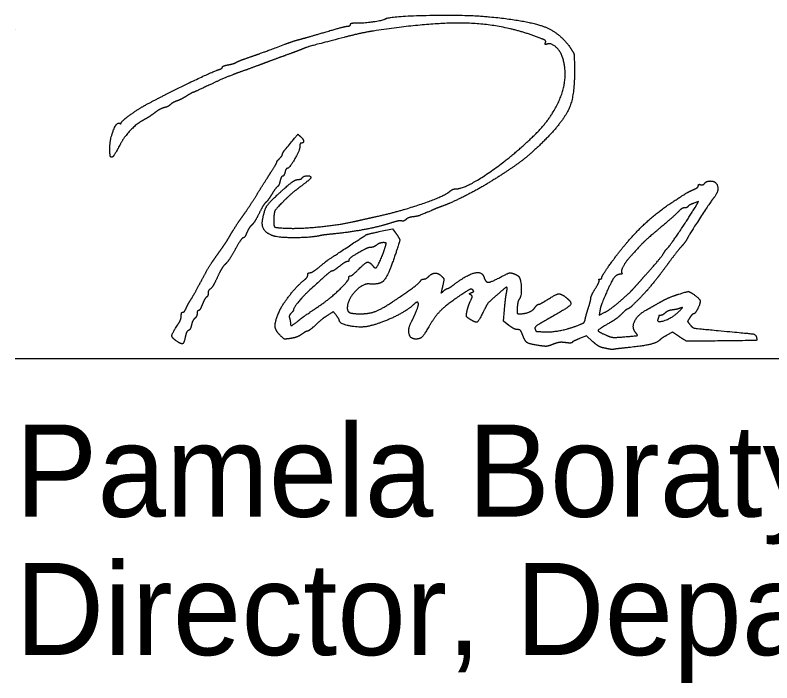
# Model space of a CAD drawing. Extents: x -11.1 to 43.5, y 0 to 22.
# Drawn here: x 24.5 to 25.648, y 7.199 to 8.213 of the extents above; entities that cross this region are included whole.
import ezdxf

# ---------------------------------------------------------------- set-up
doc = ezdxf.new("R2010")
doc.units = 0
doc.layers.add('SH_Data', color=7, linetype='Continuous')
doc.layers.add('SH_Text', color=7, linetype='Continuous')

msp = doc.modelspace()

# ---------------------------------------------------------------- linework, layer by layer
at = {"layer": 'SH_Data'}
for p, q in [((24.5, 8.191), (24.5, 8.191)), ((24.5, 7.691), (28, 7.691))]:
    msp.add_line(p, q, dxfattribs=at)
at = {"layer": 'SH_Text'}
for points in [[(25.5318, 7.9205), (25.5372, 7.9294), (25.5298, 7.9268)], [(25.0545, 7.8843), (25.0725, 7.8883), (25.0772, 7.8822)], [(25.2494, 7.7415), (25.2411, 7.7478), (25.2426, 7.7649)], [(25.3874, 7.7635), (25.3864, 7.757), (25.3951, 7.7614)], [(25.5083, 7.7242), (25.4976, 7.731), (25.4892, 7.7264)], [(25.3764, 7.7172), (25.3672, 7.7254), (25.3567, 7.7214)]]:
    msp.add_lwpolyline(points, dxfattribs=at)
for points in [[(25.0619, 8.2069), (25.0687, 8.2111), (25.1857, 8.2134), (25.2201, 8.21)], [(25.0089, 8.1984), (25.0089, 8.1998), (25.0129, 8.2008), (25.0179, 8.2007)], [(25.0179, 8.2007), (25.0275, 8.2004), (25.0585, 8.2047), (25.0619, 8.2069)], [(25.2926, 8.1792), (25.242, 8.1982), (25.1341, 8.2022), (25.0437, 8.1884)], [(25.2201, 8.21), (25.2794, 8.2041), (25.3269, 8.1858), (25.3427, 8.1628)], [(24.9721, 8.1873), (24.9882, 8.192), (25.0031, 8.1959), (25.0051, 8.1959)], [(25.0051, 8.1959), (25.0072, 8.1959), (25.0089, 8.1971), (25.0089, 8.1984)], [(24.9333, 8.1761), (24.9386, 8.1775), (24.9561, 8.1825), (24.9721, 8.1873)], [(24.9993, 8.1787), (24.9483, 8.1655), (24.944, 8.1643), (24.9333, 8.1599)], [(25.0437, 8.1884), (25.0345, 8.187), (25.0145, 8.1827), (24.9993, 8.1787)], [(25.3049, 8.1706), (25.3059, 8.1731), (25.3024, 8.1755), (25.2926, 8.1792)], [(24.8529, 8.1477), (24.8676, 8.1528), (24.8741, 8.1552), (24.9093, 8.1683)], [(24.9093, 8.1683), (24.9172, 8.1713), (24.928, 8.1748), (24.9333, 8.1761)], [(25.3073, 8.1685), (25.3047, 8.1675), (25.304, 8.1682), (25.3049, 8.1706)], [(25.3307, 8.1486), (25.3274, 8.1584), (25.313, 8.1707), (25.3073, 8.1685)], [(24.9333, 8.1599), (24.9307, 8.1589), (24.9204, 8.1551), (24.9105, 8.1515)], [(25.3427, 8.1628), (25.3476, 8.1555), (25.3486, 8.1512), (25.3489, 8.1333)], [(24.8349, 8.1405), (24.8362, 8.1415), (24.8443, 8.1448), (24.8529, 8.1477)], [(24.9105, 8.1515), (24.9006, 8.1479), (24.8855, 8.1423), (24.8769, 8.1391)], [(25.2852, 8.0274), (25.3161, 8.0568), (25.34, 8.1204), (25.3307, 8.1486)], [(24.8091, 8.1299), (24.8121, 8.1308), (24.8145, 8.1324), (24.8145, 8.1334)], [(24.8145, 8.1334), (24.8145, 8.1345), (24.8185, 8.1362), (24.8235, 8.1371)], [(24.8235, 8.1371), (24.8284, 8.138), (24.8336, 8.1396), (24.8349, 8.1405)], [(24.8769, 8.1391), (24.8683, 8.1358), (24.8521, 8.1299), (24.8409, 8.1259)], [(25.3489, 8.1333), (25.3496, 8.0926), (25.3335, 8.0529), (25.3041, 8.023)], [(24.6969, 8.0755), (24.7271, 8.0918), (24.8007, 8.1274), (24.8091, 8.1299)], [(24.8409, 8.1259), (24.8297, 8.1219), (24.8093, 8.1134), (24.7957, 8.1069)], [(24.7957, 8.1069), (24.782, 8.1004), (24.7704, 8.0951), (24.7698, 8.0951)], [(24.7598, 8.0895), (24.7549, 8.0864), (24.7482, 8.083), (24.745, 8.082)], [(24.7698, 8.0951), (24.7693, 8.0951), (24.7648, 8.0926), (24.7598, 8.0895)], [(24.6609, 8.0489), (24.6609, 8.0511), (24.6863, 8.0698), (24.6969, 8.0755)], [(24.7358, 8.0768), (24.734, 8.075), (24.7297, 8.0728), (24.7261, 8.072)], [(24.745, 8.082), (24.7418, 8.0809), (24.7376, 8.0786), (24.7358, 8.0768)], [(24.7113, 8.0639), (24.7067, 8.0603), (24.6995, 8.0557), (24.6954, 8.0536)], [(24.7261, 8.072), (24.7226, 8.0711), (24.7159, 8.0675), (24.7113, 8.0639)], [(24.6954, 8.0536), (24.685, 8.0482), (24.6651, 8.0274), (24.6589, 8.0153)], [(24.6437, 8.0111), (24.6438, 8.0242), (24.6545, 8.0508), (24.6586, 8.0483)], [(24.6586, 8.0483), (24.6599, 8.0475), (24.6609, 8.0478), (24.6609, 8.0489)], [(24.9111, 8.01), (24.9296, 8.0321), (24.9289, 8.0316), (24.933, 8.0282)], [(24.933, 8.0282), (24.9373, 8.0246), (24.9382, 8.0183), (24.9345, 8.0183)], [(24.9345, 8.0183), (24.9332, 8.0183), (24.9321, 8.0161), (24.9321, 8.0133)], [(25.1685, 7.9487), (25.1826, 7.9487), (25.2507, 7.9946), (25.2852, 8.0274)], [(25.3041, 8.023), (25.2855, 8.0041), (25.2531, 7.9792), (25.2226, 7.9603)], [(24.6451, 7.9973), (24.6443, 7.9981), (24.6437, 8.0043), (24.6437, 8.0111)], [(24.6589, 8.0153), (24.6522, 8.0024), (24.6469, 7.9955), (24.6451, 7.9973)], [(24.9057, 8.0013), (24.9057, 8.0025), (24.9081, 8.0064), (24.9111, 8.01)], [(24.9321, 8.0133), (24.9321, 8.0077), (24.9162, 7.9799), (24.913, 7.9799)], [(24.8971, 7.9895), (24.8966, 7.9895), (24.8983, 7.9917), (24.9009, 7.9943)], [(24.9009, 7.9943), (24.9035, 7.997), (24.9057, 8.0001), (24.9057, 8.0013)], [(24.8881, 7.9739), (24.8937, 7.9825), (24.8977, 7.9895), (24.8971, 7.9895)], [(24.8661, 7.9389), (24.8727, 7.9495), (24.8826, 7.9653), (24.8881, 7.9739)], [(24.9095, 7.9739), (24.9087, 7.9706), (24.907, 7.9679), (24.9058, 7.9679)], [(24.913, 7.9799), (24.9119, 7.9799), (24.9103, 7.9772), (24.9095, 7.9739)], [(24.8973, 7.939), (24.913, 7.9536), (24.9258, 7.9631), (24.9297, 7.9631)], [(24.9021, 7.9608), (24.9012, 7.9568), (24.8995, 7.953), (24.8982, 7.9522)], [(24.9058, 7.9679), (24.9047, 7.9679), (24.903, 7.9647), (24.9021, 7.9608)], [(24.9297, 7.9631), (24.9322, 7.9631), (24.9349, 7.9642), (24.9357, 7.9655)], [(24.9489, 7.9659), (24.9489, 7.9648), (24.9421, 7.9589), (24.9339, 7.9528)], [(24.9357, 7.9655), (24.9375, 7.9684), (24.9489, 7.9688), (24.9489, 7.9659)], [(25.2226, 7.9603), (25.2035, 7.9485), (25.1622, 7.9275), (25.1481, 7.9224)], [(25.5466, 7.9573), (25.5482, 7.9592), (25.5519, 7.9607), (25.5548, 7.9607)], [(25.5548, 7.9607), (25.5643, 7.9607), (25.568, 7.9447), (25.5606, 7.9357)], [(24.8982, 7.9522), (24.8969, 7.9514), (24.8931, 7.9462), (24.8897, 7.9407)], [(24.9339, 7.9528), (24.9256, 7.9467), (24.9131, 7.9358), (24.9061, 7.9287)], [(25.1603, 7.9454), (25.1624, 7.9472), (25.1661, 7.9487), (25.1685, 7.9487)], [(25.5001, 7.9304), (25.5191, 7.9426), (25.5209, 7.9437), (25.5291, 7.9474)], [(25.5291, 7.9474), (25.5334, 7.9493), (25.5369, 7.9521), (25.5369, 7.9537)], [(25.5369, 7.9537), (25.5369, 7.9552), (25.5384, 7.9559), (25.5403, 7.9551)], [(25.5403, 7.9551), (25.5422, 7.9544), (25.545, 7.9554), (25.5466, 7.9573)], [(24.8443, 7.9059), (24.8497, 7.9134), (24.8595, 7.9282), (24.8661, 7.9389)], [(24.876, 7.9043), (24.8787, 7.9174), (24.8849, 7.9274), (24.8973, 7.939)], [(24.8897, 7.9407), (24.8863, 7.9352), (24.8822, 7.9296), (24.8806, 7.9283)], [(25.0485, 7.9068), (25.0854, 7.915), (25.1517, 7.9379), (25.1603, 7.9454)], [(24.8806, 7.9283), (24.8789, 7.927), (24.8742, 7.9194), (24.8702, 7.9114)], [(24.9061, 7.9287), (24.8954, 7.9177), (24.8932, 7.914), (24.8927, 7.9058)], [(25.4055, 7.8378), (25.4278, 7.8686), (25.4728, 7.9127), (25.5001, 7.9304)], [(25.5606, 7.9357), (25.5564, 7.9307), (25.5236, 7.8802), (25.5204, 7.8741)], [(25.5298, 7.9268), (25.5258, 7.9254), (25.5219, 7.9233), (25.5212, 7.9221)], [(25.1325, 7.9162), (25.1154, 7.9088), (25.1105, 7.9071), (25.1039, 7.9063)], [(25.1481, 7.9224), (25.1435, 7.9207), (25.1364, 7.918), (25.1325, 7.9162)], [(25.507, 7.9145), (25.5043, 7.9116), (25.4918, 7.9005), (25.4793, 7.89)], [(25.489, 7.8575), (25.4918, 7.8595), (25.52, 7.901), (25.5318, 7.9205)], [(25.5158, 7.9199), (25.5136, 7.9199), (25.5097, 7.9175), (25.507, 7.9145)], [(25.5212, 7.9221), (25.5204, 7.9209), (25.518, 7.9199), (25.5158, 7.9199)], [(24.8276, 7.8803), (24.8315, 7.8869), (24.839, 7.8985), (24.8443, 7.9059)], [(24.8702, 7.9114), (24.8662, 7.9034), (24.8611, 7.8954), (24.859, 7.8936)], [(24.8913, 7.8775), (24.8809, 7.8814), (24.8737, 7.8938), (24.876, 7.9043)], [(24.8927, 7.9058), (24.8918, 7.8923), (24.8959, 7.8895), (24.9165, 7.8889)], [(25.0149, 7.8993), (25.0228, 7.9011), (25.0379, 7.9045), (25.0485, 7.9068)], [(25.0931, 7.9022), (25.091, 7.9004), (25.0879, 7.8995), (25.0863, 7.9001)], [(25.1039, 7.9063), (25.1, 7.9059), (25.0952, 7.9041), (25.0931, 7.9022)], [(24.859, 7.8936), (24.8568, 7.8918), (24.8535, 7.8867), (24.8517, 7.8823)], [(24.9165, 7.8889), (24.9358, 7.8884), (24.9936, 7.8945), (25.0149, 7.8993)], [(25.0683, 7.8963), (25.0518, 7.891), (25.0067, 7.8826), (24.9829, 7.8803)], [(25.0863, 7.9001), (25.0846, 7.9007), (25.0765, 7.899), (25.0683, 7.8963)], [(25.4793, 7.89), (25.4597, 7.8734), (25.448, 7.862), (25.4313, 7.8432)], [(24.8146, 7.8597), (24.8179, 7.8645), (24.8238, 7.8737), (24.8276, 7.8803)], [(24.8517, 7.8823), (24.8498, 7.8779), (24.8473, 7.8743), (24.846, 7.8743)], [(24.9829, 7.8803), (24.9746, 7.8795), (24.9654, 7.8783), (24.9625, 7.8776)], [(25.0005, 7.8579), (25.0322, 7.8789), (25.0335, 7.8796), (25.0545, 7.8843)], [(25.0772, 7.8822), (25.0838, 7.8734), (25.0836, 7.8685), (25.0759, 7.846)], [(24.846, 7.8743), (24.8447, 7.8743), (24.8393, 7.8664), (24.8339, 7.8568)], [(24.9625, 7.8776), (24.9488, 7.8746), (24.8993, 7.8745), (24.8913, 7.8775)], [(25.0585, 7.8671), (25.0557, 7.867), (25.0512, 7.8654), (25.0486, 7.8635)], [(25.0618, 7.8605), (25.0635, 7.8663), (25.0631, 7.8671), (25.0585, 7.8671)], [(25.5204, 7.8741), (25.5187, 7.8706), (25.5148, 7.8652), (25.5118, 7.8619)], [(24.801, 7.8405), (24.8051, 7.8463), (24.8112, 7.8549), (24.8146, 7.8597)], [(24.8339, 7.8568), (24.8286, 7.8471), (24.8219, 7.8371), (24.8191, 7.8346)], [(24.9613, 7.83), (24.975, 7.841), (24.973, 7.8396), (25.0005, 7.8579)], [(25.0302, 7.8568), (25.0158, 7.8489), (25.0065, 7.8425), (25.0065, 7.8405)], [(25.0399, 7.8599), (25.0377, 7.8599), (25.0333, 7.8585), (25.0302, 7.8568)], [(25.0486, 7.8635), (25.0461, 7.8615), (25.0421, 7.8599), (25.0399, 7.8599)], [(25.0471, 7.8287), (25.0489, 7.8287), (25.0587, 7.8499), (25.0618, 7.8605)], [(25.4851, 7.8524), (25.4863, 7.8546), (25.4881, 7.8569), (25.489, 7.8575)], [(25.5118, 7.8619), (25.5088, 7.8587), (25.4999, 7.8474), (25.492, 7.8367)], [(25.0759, 7.846), (25.0656, 7.8161), (25.0537, 7.803), (25.0377, 7.8044)], [(25.4538, 7.8146), (25.4691, 7.8317), (25.4827, 7.8481), (25.4851, 7.8524)], [(24.7821, 7.8083), (24.7884, 7.8202), (24.7969, 7.8347), (24.801, 7.8405)], [(24.8191, 7.8346), (24.8162, 7.832), (24.8107, 7.8229), (24.8068, 7.8143)], [(25.0038, 7.8383), (25.0024, 7.8383), (24.9971, 7.8351), (24.9921, 7.8311)], [(25.0065, 7.8405), (25.0065, 7.8393), (25.0053, 7.8383), (25.0038, 7.8383)], [(25.0209, 7.8263), (25.031, 7.8365), (25.0376, 7.8383), (25.0425, 7.8323)], [(25.3905, 7.8145), (25.3905, 7.8159), (25.3972, 7.8264), (25.4055, 7.8378)], [(25.4313, 7.8432), (25.4255, 7.8366), (25.4192, 7.8237), (25.4206, 7.8213)], [(25.492, 7.8367), (25.4841, 7.8261), (25.4765, 7.8159), (25.475, 7.814)], [(24.9441, 7.8181), (24.9441, 7.82), (24.9456, 7.8215), (24.9475, 7.8215)], [(24.981, 7.8239), (24.9791, 7.8239), (24.9706, 7.8167), (24.9453, 7.7934)], [(24.9475, 7.8215), (24.9493, 7.8215), (24.9555, 7.8253), (24.9613, 7.83)], [(24.9921, 7.8311), (24.9871, 7.8272), (24.9821, 7.8239), (24.981, 7.8239)], [(25.0089, 7.8167), (25.0102, 7.8167), (25.0156, 7.8211), (25.0209, 7.8263)], [(25.0425, 7.8323), (25.0441, 7.8304), (25.0462, 7.8287), (25.0471, 7.8287)], [(25.1657, 7.8033), (25.1859, 7.8184), (25.2086, 7.824), (25.2116, 7.8146)], [(25.2354, 7.8142), (25.2474, 7.8208), (25.2546, 7.8216), (25.2628, 7.817)], [(25.4206, 7.8213), (25.4214, 7.8201), (25.4204, 7.8191), (25.4184, 7.8191)], [(24.8068, 7.8143), (24.8029, 7.8058), (24.7981, 7.7979), (24.7963, 7.7968)], [(24.9006, 7.7621), (24.9051, 7.7725), (24.9283, 7.802), (24.9387, 7.8103)], [(24.9387, 7.8103), (24.9417, 7.8127), (24.9441, 7.8162), (24.9441, 7.8181)], [(24.9604, 7.7702), (24.976, 7.7806), (25.0065, 7.8093), (25.0065, 7.8136)], [(25.0065, 7.8136), (25.0065, 7.8153), (25.0076, 7.8167), (25.0089, 7.8167)], [(25.1152, 7.8089), (25.1163, 7.8106), (25.1186, 7.8119), (25.1204, 7.8119)], [(25.1204, 7.8119), (25.1223, 7.8119), (25.1255, 7.8137), (25.1277, 7.8158)], [(25.1277, 7.8158), (25.1326, 7.8208), (25.1426, 7.8209), (25.1475, 7.8159)], [(25.1475, 7.8159), (25.1507, 7.8128), (25.1509, 7.8103), (25.1488, 7.8011)], [(25.2116, 7.8146), (25.214, 7.807), (25.2221, 7.8069), (25.2354, 7.8142)], [(25.2628, 7.817), (25.2672, 7.8145), (25.2689, 7.7865), (25.265, 7.7813)], [(25.3807, 7.7976), (25.3846, 7.8039), (25.3871, 7.8097), (25.3863, 7.8105)], [(25.3863, 7.8105), (25.3855, 7.8113), (25.3862, 7.8119), (25.3877, 7.8119)], [(25.3877, 7.8119), (25.3892, 7.8119), (25.3905, 7.8131), (25.3905, 7.8145)], [(25.4184, 7.8191), (25.412, 7.8191), (25.4025, 7.804), (25.3904, 7.7747)], [(25.4382, 7.7971), (25.4413, 7.8006), (25.4484, 7.8085), (25.4538, 7.8146)], [(25.475, 7.814), (25.4617, 7.7976), (25.4572, 7.7925), (25.4453, 7.7803)], [(24.7667, 7.7807), (24.7689, 7.784), (24.7759, 7.7965), (24.7821, 7.8083)], [(25.0377, 7.8044), (25.0273, 7.8053), (25.0041, 7.7799), (25.0041, 7.7676)], [(25.0725, 7.7771), (25.0911, 7.7894), (25.1135, 7.8061), (25.1152, 7.8089)], [(25.1488, 7.8011), (25.1465, 7.7909), (25.1466, 7.7904), (25.1504, 7.7939)], [(25.1562, 7.7975), (25.1572, 7.7975), (25.1615, 7.8001), (25.1657, 7.8033)], [(25.2455, 7.7897), (25.2474, 7.7992), (25.2447, 7.7996), (25.2354, 7.7914)], [(24.7929, 7.7904), (24.7929, 7.7879), (24.7918, 7.7851), (24.7904, 7.7843)], [(24.7963, 7.7968), (24.7944, 7.7958), (24.7929, 7.7929), (24.7929, 7.7904)], [(24.9453, 7.7934), (24.9362, 7.785), (24.9225, 7.768), (24.9225, 7.765)], [(25.1504, 7.7939), (25.1526, 7.7959), (25.1553, 7.7975), (25.1562, 7.7975)], [(25.1943, 7.7955), (25.1925, 7.7973), (25.1866, 7.7945), (25.1741, 7.786)], [(25.1915, 7.7878), (25.1893, 7.7892), (25.1896, 7.7901), (25.1927, 7.7913)], [(25.1908, 7.778), (25.1937, 7.7842), (25.1938, 7.7864), (25.1915, 7.7878)], [(25.1927, 7.7913), (25.1957, 7.7924), (25.1962, 7.7936), (25.1943, 7.7955)], [(25.2354, 7.7914), (25.2195, 7.7774), (25.2158, 7.773), (25.2103, 7.7616)], [(25.2426, 7.7649), (25.2434, 7.7743), (25.2447, 7.7854), (25.2455, 7.7897)], [(25.3081, 7.7807), (25.321, 7.789), (25.3286, 7.7898), (25.3363, 7.7837)], [(25.3737, 7.7829), (25.3737, 7.7847), (25.3769, 7.7914), (25.3807, 7.7976)], [(25.4181, 7.7783), (25.426, 7.7851), (25.4351, 7.7936), (25.4382, 7.7971)], [(25.4781, 7.7763), (25.486, 7.7808), (25.4992, 7.7865), (25.5074, 7.789)], [(25.5074, 7.789), (25.5215, 7.7932), (25.5226, 7.7932), (25.5285, 7.7894)], [(25.5285, 7.7894), (25.5381, 7.7831), (25.5405, 7.7757), (25.5359, 7.7667)], [(24.7598, 7.7681), (24.7614, 7.7718), (24.7645, 7.7774), (24.7667, 7.7807)], [(24.7904, 7.7843), (24.789, 7.7834), (24.7862, 7.7785), (24.7841, 7.7733)], [(25.024, 7.7591), (25.0371, 7.7591), (25.0562, 7.7662), (25.0725, 7.7771)], [(25.1121, 7.7738), (25.1121, 7.7769), (25.1081, 7.7764), (25.1045, 7.7729)], [(25.1741, 7.786), (25.1544, 7.7726), (25.1372, 7.7555), (25.1289, 7.7411)], [(25.1857, 7.7623), (25.1865, 7.7665), (25.1888, 7.7736), (25.1908, 7.778)], [(25.265, 7.7813), (25.2637, 7.7797), (25.2624, 7.774), (25.262, 7.7687)], [(25.2945, 7.7735), (25.2957, 7.7735), (25.3018, 7.7768), (25.3081, 7.7807)], [(25.3363, 7.7837), (25.346, 7.7761), (25.3391, 7.7682), (25.3076, 7.7505)], [(25.3702, 7.7687), (25.3721, 7.7747), (25.3737, 7.781), (25.3737, 7.7829)], [(25.3951, 7.7614), (25.3998, 7.7639), (25.4102, 7.7715), (25.4181, 7.7783)], [(25.4453, 7.7803), (25.4378, 7.7726), (25.4308, 7.7663), (25.4297, 7.7663)], [(25.4585, 7.7653), (25.4614, 7.7668), (25.4702, 7.7718), (25.4781, 7.7763)], [(24.7545, 7.7615), (24.7559, 7.7615), (24.7583, 7.7645), (24.7598, 7.7681)], [(24.7782, 7.7639), (24.7771, 7.7639), (24.7761, 7.7619), (24.7761, 7.7594)], [(24.7841, 7.7733), (24.7821, 7.7682), (24.7794, 7.7639), (24.7782, 7.7639)], [(24.9225, 7.765), (24.9225, 7.7642), (24.9208, 7.7619), (24.9188, 7.7599)], [(24.9289, 7.7478), (24.9364, 7.7539), (24.9417, 7.7576), (24.9604, 7.7702)], [(25.0041, 7.7676), (25.0041, 7.7625), (25.0119, 7.7591), (25.024, 7.7591)], [(25.1045, 7.7729), (25.0949, 7.7638), (25.0562, 7.745), (25.0377, 7.7405)], [(25.1015, 7.7471), (25.1056, 7.7548), (25.1121, 7.7711), (25.1121, 7.7738)], [(25.262, 7.7687), (25.2615, 7.7612), (25.2622, 7.7591), (25.2654, 7.7591)], [(25.2654, 7.7591), (25.2737, 7.7591), (25.2857, 7.764), (25.289, 7.7687)], [(25.289, 7.7687), (25.2908, 7.7713), (25.2933, 7.7735), (25.2945, 7.7735)], [(25.3654, 7.7517), (25.3661, 7.7551), (25.3683, 7.7628), (25.3702, 7.7687)], [(25.3904, 7.7747), (25.3893, 7.7721), (25.388, 7.767), (25.3874, 7.7635)], [(25.4297, 7.7663), (25.4286, 7.7663), (25.4247, 7.7632), (25.4211, 7.7594)], [(25.4415, 7.7309), (25.4354, 7.7383), (25.4452, 7.7581), (25.4585, 7.7653)], [(25.4975, 7.7649), (25.4936, 7.7644), (25.4887, 7.7623), (25.4865, 7.7603)], [(25.5093, 7.7676), (25.5067, 7.7666), (25.5013, 7.7654), (25.4975, 7.7649)], [(25.5069, 7.7621), (25.5124, 7.7676), (25.513, 7.769), (25.5093, 7.7676)], [(25.5359, 7.7667), (25.5337, 7.7625), (25.531, 7.7591), (25.5299, 7.7591)], [(24.7463, 7.7416), (24.7495, 7.7464), (24.7521, 7.7528), (24.7521, 7.7559)], [(24.7521, 7.7559), (24.7521, 7.759), (24.7532, 7.7615), (24.7545, 7.7615)], [(24.7727, 7.7521), (24.7708, 7.7505), (24.7685, 7.746), (24.7676, 7.742)], [(24.7761, 7.7594), (24.7761, 7.757), (24.7745, 7.7536), (24.7727, 7.7521)], [(24.9023, 7.7264), (24.8947, 7.734), (24.8941, 7.7468), (24.9006, 7.7621)], [(24.9188, 7.7599), (24.9167, 7.7578), (24.9156, 7.7546), (24.9164, 7.7526)], [(24.9164, 7.7526), (24.9171, 7.7507), (24.9177, 7.7476), (24.9177, 7.7457)], [(24.9762, 7.758), (24.968, 7.7526), (24.9654, 7.7506), (24.9542, 7.7405)], [(24.9875, 7.7566), (24.983, 7.7624), (24.983, 7.7624), (24.9762, 7.758)], [(24.992, 7.7492), (24.992, 7.75), (24.99, 7.7534), (24.9875, 7.7566)], [(25.1903, 7.7508), (25.1853, 7.7541), (25.1845, 7.7561), (25.1857, 7.7623)], [(25.2103, 7.7616), (25.2036, 7.7479), (25.1988, 7.7453), (25.1903, 7.7508)], [(25.4211, 7.7594), (25.4175, 7.7556), (25.4094, 7.7494), (25.4031, 7.7458)], [(25.4755, 7.751), (25.473, 7.7445), (25.4984, 7.7534), (25.5069, 7.7621)], [(25.4769, 7.7557), (25.4769, 7.7552), (25.4763, 7.7531), (25.4755, 7.751)], [(25.4797, 7.7567), (25.4782, 7.7567), (25.4769, 7.7563), (25.4769, 7.7557)], [(25.4865, 7.7603), (25.4843, 7.7584), (25.4813, 7.7567), (25.4797, 7.7567)], [(25.524, 7.7533), (25.5205, 7.748), (25.5206, 7.7471), (25.5244, 7.7424)], [(25.5299, 7.7591), (25.5288, 7.7591), (25.5261, 7.7565), (25.524, 7.7533)], [(24.7446, 7.7179), (24.7376, 7.7228), (24.7381, 7.7295), (24.7463, 7.7416)], [(24.7676, 7.742), (24.7668, 7.7381), (24.7646, 7.7343), (24.7629, 7.7336)], [(24.9177, 7.7457), (24.9177, 7.7409), (24.9211, 7.7415), (24.9289, 7.7478)], [(25.0377, 7.7405), (25.0248, 7.7374), (24.9922, 7.7436), (24.992, 7.7492)], [(25.1082, 7.7207), (25.0998, 7.7207), (25.0958, 7.7365), (25.1015, 7.7471)], [(25.1289, 7.7411), (25.1207, 7.727), (25.1143, 7.7207), (25.1082, 7.7207)], [(25.2624, 7.7351), (25.2599, 7.7351), (25.254, 7.738), (25.2494, 7.7415)], [(25.3076, 7.7505), (25.2943, 7.743), (25.2881, 7.7382), (25.289, 7.736)], [(25.3029, 7.7317), (25.3134, 7.7311), (25.3396, 7.736), (25.3527, 7.741)], [(25.3527, 7.741), (25.3615, 7.7444), (25.3645, 7.7469), (25.3654, 7.7517)], [(25.4031, 7.7458), (25.3852, 7.7354), (25.3842, 7.7321), (25.3971, 7.7266)], [(25.5244, 7.7424), (25.528, 7.7379), (25.533, 7.7368), (25.5669, 7.7337)], [(24.7629, 7.7336), (24.7612, 7.7329), (24.7591, 7.7288), (24.7583, 7.7244)], [(24.9435, 7.7327), (24.9424, 7.7327), (24.9386, 7.7306), (24.935, 7.728)], [(24.9542, 7.7405), (24.9494, 7.7362), (24.9446, 7.7327), (24.9435, 7.7327)], [(25.27, 7.7273), (25.2681, 7.7325), (25.2656, 7.7351), (25.2624, 7.7351)], [(25.289, 7.736), (25.2903, 7.7326), (25.291, 7.7324), (25.3029, 7.7317)], [(25.4239, 7.7241), (25.4434, 7.7257), (25.4452, 7.7264), (25.4415, 7.7309)], [(25.5669, 7.7337), (25.616, 7.7292), (25.6243, 7.7276), (25.6252, 7.7228)], [(24.7583, 7.7244), (24.7564, 7.7146), (24.7522, 7.7127), (24.7446, 7.7179)], [(24.9185, 7.7217), (24.9098, 7.7204), (24.9076, 7.721), (24.9023, 7.7264)], [(24.935, 7.728), (24.9314, 7.7254), (24.924, 7.7226), (24.9185, 7.7217)], [(25.2953, 7.7108), (25.2803, 7.7132), (25.2735, 7.7177), (25.27, 7.7273)], [(25.3567, 7.7214), (25.3509, 7.7191), (25.3458, 7.7165), (25.3454, 7.7156)], [(25.3971, 7.7266), (25.4039, 7.7236), (25.4104, 7.723), (25.4239, 7.7241)], [(25.4775, 7.7186), (25.4738, 7.7149), (25.4523, 7.71), (25.4289, 7.7076)], [(25.4892, 7.7264), (25.4846, 7.724), (25.4794, 7.7204), (25.4775, 7.7186)], [(25.5549, 7.7177), (25.5192, 7.7174), (25.5188, 7.7174), (25.5083, 7.7242)], [(25.6252, 7.7228), (25.626, 7.7186), (25.624, 7.7185), (25.5549, 7.7177)], [(25.3164, 7.7128), (25.3094, 7.71), (25.3039, 7.7094), (25.2953, 7.7108)], [(25.3353, 7.7153), (25.3295, 7.7161), (25.3222, 7.7151), (25.3164, 7.7128)], [(25.3454, 7.7156), (25.345, 7.7148), (25.3404, 7.7146), (25.3353, 7.7153)], [(25.391, 7.7077), (25.388, 7.7083), (25.3814, 7.7126), (25.3764, 7.7172)], [(25.4013, 7.7055), (25.3987, 7.7061), (25.394, 7.7071), (25.391, 7.7077)], [(25.4289, 7.7076), (25.4203, 7.7067), (25.4117, 7.7057), (25.4097, 7.7053)], [(25.4097, 7.7053), (25.4077, 7.7049), (25.4039, 7.705), (25.4013, 7.7055)]]:
    msp.add_open_spline(points, degree=2, dxfattribs=at)

# ---------------------------------------------------------------- texts
for s, p in [('Pamela Boratyn', (24.5, 7.451)), ('Director, Department of Transportation', (24.5, 7.241))]:
    msp.add_text(s, height=0.14, dxfattribs=at).set_placement(p)

doc.saveas('drawing.dxf')
